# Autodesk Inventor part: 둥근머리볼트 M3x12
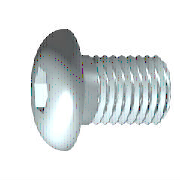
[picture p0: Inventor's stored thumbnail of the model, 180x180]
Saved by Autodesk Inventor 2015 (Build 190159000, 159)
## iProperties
IsCustomPart: 0
Created: 2012-02
Part Number: 둥근머리볼트 M3x12
Material: 강철
Description: 6각 소켓 버튼 머리 나사 - 제품 등급 A
Document SubType Name: Modeling
Standard: ISO 7380
Designer: mduedu
Standard Revision: Third edition 2004-01-15
Standards Organization: ISO
Language: ko-KR
Size Designation: M3 x 12
Categories: <MemberInstance><Categories><Category DisplayName="조임쇠" InternalName="e4da775c-781d-43d5-af7c-5136215cf5a6" Mnemonic="FSTN"><Category DisplayName="볼트" InternalN
Density: 7.85 g/cm^3
Appearance: 강철
Mass: 0.90169 g
Surface Area: 1.87531 cm^2
Volume: 0.114865 cm^3
Author: mduedu
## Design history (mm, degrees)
sketch "스케치1"
  geometry: L1 (0.057, 0)-(12, 0); L2 (12, 0)-(12, 1.5); L3 (12, 1.5)-(1, 1.5); L4 (1, 1.5)-(0.693, 1.5); L5 (0.693, 1.5)-(0, 1.5); L6 (0, 1.5)-(0, 2.85); L7 (0, 2.85)-(-1.65, 2.85); L8 (-1.65, 2.85)-(-1.65, 1.155); L9 (-1.65, 1.155)-(-0.61, 1.155); L10 (-0.61, 1.155)-(0.057, 0); L11 (-4.38, 0)-(14.73, 0) reference; L12 (0, -0.57)-(0, 3.42) reference; L13 (1, 1.5)-(0, 1.5)
  constraints: 22 end point, 6 parallel, 2 collinear, 2 perpendicular, 1 horizontal, 1 point on line
  dimensions: "d1" = 11 distance from line of L3.end L2 (= GEL); "d2" = 0.30683 distance of L4.end L3.end (computed from GAL); "d3" = 1.65 distance between parallel lines of L8 L6 (= KOH); "d4" = 1.04 distance of L8.end L9.end (= INTI); "d5" = 60 deg angle of L10 L1; "d6" = 3 diameter of L3 L1 (= GD); "d7" = 3 diameter of L5 L1 (= BDM); "d8" = 2.3094 diameter of L9 L1 (= 1.1547 x SW); "d9" = 5.7 diameter of L7 L1 (= KOD); "d26" = 12 distance between parallel lines of L12 L2 (= NLG)
revolve "본체" sketch "스케치1" stored, may be unused: angle "d10" = 90 deg
sketch "스케치2"
  geometry: L1 (0, -3.99)-(0, 3.99) reference; L2 (-3.99, 0)-(3.99, 0) reference; L3 (1.155, 0)-(0.577, -1); L4 (0.577, -1)-(-0.577, -1); L5 (-0.577, -1)-(-1.155, 0); L6 (-1.155, 0)-(-0.577, 1); L7 (-0.577, 1)-(0.577, 1); L8 (0.577, 1)-(1.155, 0); 2 further points
  constraints: 12 end point, 1 coincident, 1 horizontal alignment, 1 point on line, 12 other
extrude "슬롯" join sketch "스케치2" stored distance "d11" = 10; taper "d12" = 0 deg
workplane "Work Plane1"
body "Solid1"
fillet "모깎기1" dims "d17" = 1.45 (= RR)
feature "스레드" dims "d13" = 11 (= GEL), "d14" = 0
chamfer "모따기1" distance "d15" = 0.30673 (= -0.5 x SPD + 0.5 x GD); stored, may be unused: second distance "d16" = 0.30673 (= GUL), angle "d27" = 45 deg
fillet "모깎기2" dims "d30" = 0.1 (= R)
other parameters: "GD" = 3 (= NND) [user parameter; used in 2 equation terms], "NLG" = 12 [user parameter; used in 1 equation term], "GEL" = 11 [user parameter; used in 2 equation terms], "KOD" = 5.7 [user parameter; used in 1 equation term], "KOH" = 1.65 [user parameter; used in 1 equation term], "INTI" = 1.04 [user parameter; used in 1 equation term], "GAL" = 0.30673 (= 0.61345 x PTC) [user parameter; used in 1 equation term], "GUL" = 0.30673 (= 0.61345 x PTC) [user parameter; used in 1 equation term], "BDM" = 3 (= NND) [user parameter; used in 1 equation term], "SW" = 2 [user parameter; used in 1 equation term], "RR" = 1.45 [user parameter; used in 1 equation term], "SPD" = 2.38655 (= NND - 1.2269 x PTC) [user parameter; used in 1 equation term], "d19" = 0, "d28" = 0, "d29" = 0, "R" = 0.1 [user parameter; used in 1 equation term], "TOA" = 30 deg [user parameter], "GD1" = 2.38655 (= THREADDIA - 1.2269 x PTC) [user parameter], "THREADDIA" = 3 [user parameter; used in 1 equation term], "PTC" = 0.5 [user parameter; used in 5 equation terms], "NND" = 3 [user parameter; used in 3 equation terms], "KOH1" = 0.2 [user parameter], "E0" = 2.31 [user parameter]
